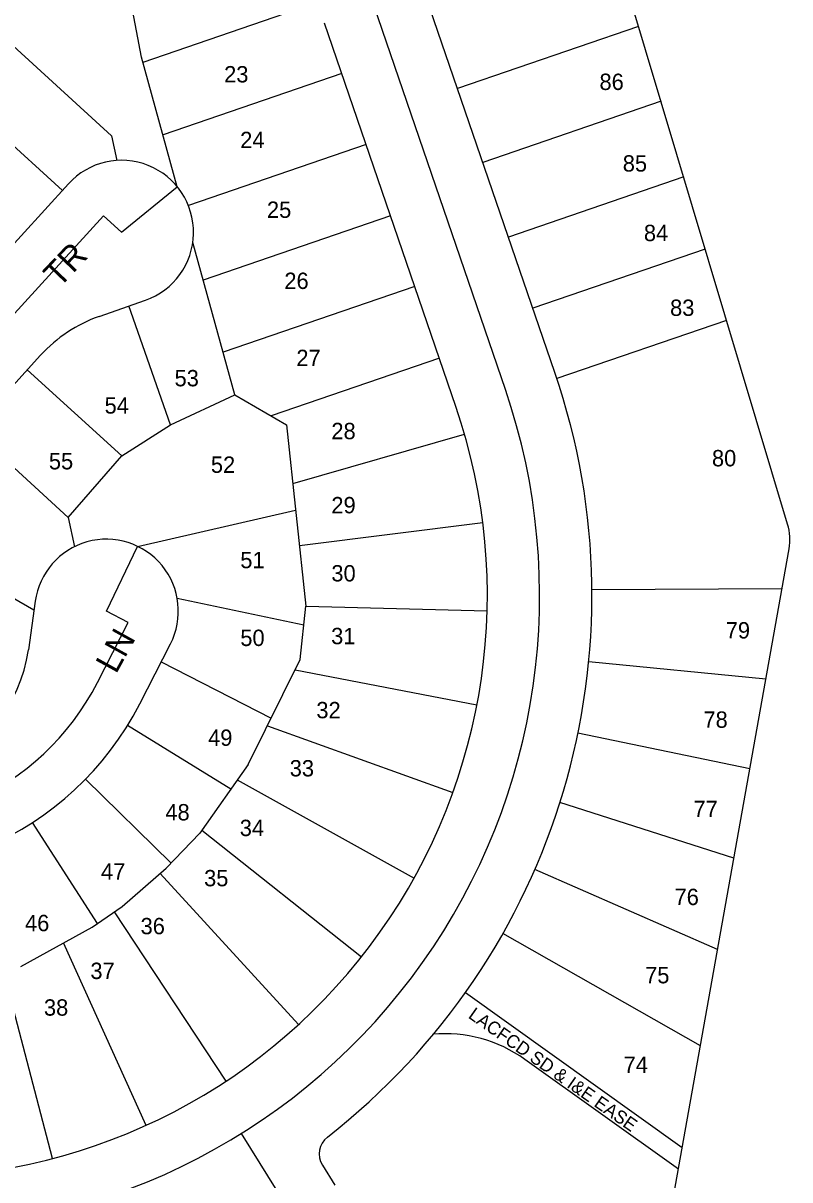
# Model space of a CAD drawing. Extents: x 6387474 to 6390971, y 1972046 to 1973920.
# Drawn here: x 6389408 to 6389877, y 1972544 to 1973251 of the extents above; entities that cross this region are included whole.
import ezdxf

# ---------------------------------------------------------------- set-up
doc = ezdxf.new("R2010")
doc.units = 0
for name, color, linetype in [('1', 7, 'Continuous'), ('2', 7, 'Continuous'), ('3', 7, 'Continuous'), ('4', 7, 'Continuous'), ('5', 7, 'Continuous'), ('7', 7, 'Continuous')]:
    doc.layers.add(name, color=color, linetype=linetype)

msp = doc.modelspace()

# ---------------------------------------------------------------- linework, layer by layer
at = {"layer": '1'}
for p, q in [((6389875.29, 1972944.72), (6389740.69, 1973394.07)), ((6389759.25, 1972274.95), (6389876.15, 1972929.69))]:
    msp.add_line(p, q, dxfattribs=at)
msp.add_arc((6389844.16, 1972935.4), 32.5, 349.87611, 16.67291, dxfattribs=at)
at = {"layer": '2'}
for p, q in [((6389702.59, 1973027.14), (6389622.23, 1973261.52)), ((6389467.81, 1973123.26), (6389501.88, 1973151.11)), ((6389350.37, 1973016.66), (6389456.72, 1973133.37)), ((6389456.72, 1973133.37), (6389467.81, 1973123.26)), ((6389458.5, 1972891.57), (6389477.61, 1972931.2)), ((6389471.85, 1972884.72), (6389458.5, 1972891.57)), ((6389453.05, 1972848.05), (6389471.85, 1972884.72)), ((6389540.91, 1972572.1), (6389571.1, 1972523.69))]:
    msp.add_line(p, q, dxfattribs=at)
for centre, radius, start, end in [((6389335.56, 1972901.3), 388, 270.34667, 18.92365), ((6389310.66, 1972921.02), 160, 255.09194, 332.86738)]:
    msp.add_arc(centre, radius, start, end, dxfattribs=at)
at = {"layer": '3'}
for p, q in [((6389461.63, 1973182.31), (6389072.67, 1973536.78)), ((6389431.59, 1973148.83), (6389073.04, 1973475.59)), ((6389479.97, 1973230.27), (6389463.19, 1973318.92)), ((6389587.7, 1973263.79), (6389480.83, 1973227.16)), ((6389784.1, 1973249.17), (6389673.32, 1973211.19)), ((6389501.88, 1973151.11), (6389479.97, 1973230.27)), ((6389602.55, 1973220.27), (6389493.12, 1973182.75)), ((6389797.82, 1973203.34), (6389688.82, 1973165.97)), ((6389461.63, 1973182.31), (6389464.96, 1973167.17)), ((6389617.39, 1973176.98), (6389508.63, 1973139.69)), ((6389811.68, 1973157.08), (6389704.47, 1973120.32)), ((6389632.39, 1973133.23), (6389517.73, 1973093.92)), ((6389537.14, 1973023.81), (6389511.36, 1973116.96)), ((6389824.9, 1973112.96), (6389719.4, 1973076.79)), ((6389647.18, 1973090.09), (6389529.92, 1973049.89)), ((6389497.8, 1973005.51), (6389472.27, 1973078.19)), ((6389837.95, 1973069.4), (6389734.12, 1973033.8)), ((6389662.21, 1973046.24), (6389559.25, 1973010.94)), ((6389467.88, 1972986.49), (6389410.1, 1973039.15)), ((6389497.8, 1973005.51), (6389537.14, 1973023.81)), ((6389537.14, 1973023.81), (6389568.62, 1973005.49)), ((6389435.19, 1972948.92), (6389376.6, 1973002.32)), ((6389467.88, 1972986.49), (6389497.8, 1973005.51)), ((6389568.62, 1973005.49), (6389580.57, 1972894.73)), ((6389572.49, 1972969.58), (6389677.64, 1972999.89)), ((6389435.19, 1972948.92), (6389467.88, 1972986.49)), ((6389477.61, 1972931.2), (6389574.24, 1972953.37)), ((6389435.19, 1972948.92), (6389438.99, 1972931.01)), ((6389576.59, 1972931.67), (6389688.77, 1972945.82)), ((6389327.99, 1972942.3), (6389414.18, 1972892.32)), ((6389871.79, 1972905.24), (6389755.55, 1972904.52)), ((6389579.32, 1972883.05), (6389501.8, 1972899.34)), ((6389577.07, 1972861.96), (6389580.57, 1972894.73)), ((6389580.57, 1972894.73), (6389691.43, 1972891.77)), ((6389492.05, 1972860.55), (6389559.27, 1972826.11)), ((6389545.23, 1972797.84), (6389577.07, 1972861.96)), ((6389861.92, 1972849.96), (6389753.59, 1972860.66)), ((6389573.94, 1972855.67), (6389685.21, 1972834.37)), ((6389534.62, 1972782.8), (6389471.49, 1972821.75)), ((6389556.99, 1972821.53), (6389670.49, 1972780.65)), ((6389852.15, 1972795.24), (6389747.01, 1972816.96)), ((6389545.23, 1972797.84), (6389515.64, 1972755.89)), ((6389498.05, 1972737.54), (6389445.71, 1972788.8)), ((6389538.59, 1972788.43), (6389646.71, 1972728.33)), ((6389842.4, 1972740.64), (6389735.97, 1972774.52)), ((6389453.11, 1972700.64), (6389413.27, 1972762.3)), ((6389495.15, 1972734.52), (6389515.69, 1972755.91)), ((6389516.83, 1972757.58), (6389614.55, 1972680.16)), ((6389468.1, 1972710.93), (6389495.15, 1972734.52)), ((6389576.07, 1972638.83), (6389491.35, 1972731.23)), ((6389832.42, 1972684.77), (6389720.64, 1972733.64)), ((6389449.77, 1972698.35), (6389468.1, 1972710.93)), ((6389531.81, 1972604.28), (6389463.42, 1972707.74)), ((6389406.07, 1972674.39), (6389449.77, 1972698.35)), ((6389482.78, 1972577.17), (6389432.14, 1972688.69)), ((6389821.9, 1972625.84), (6389701.09, 1972694.44)), ((6389425.58, 1972556.87), (6389395.79, 1972670.93)), ((6389810.75, 1972563.4), (6389678.1, 1972658.27))]:
    msp.add_line(p, q, dxfattribs=at)
at = {"layer": '4'}
for p, q in [((6389732.86, 1973037.51), (6389652.51, 1973271.9)), ((6389672.32, 1973016.76), (6389591.96, 1973251.15)), ((6389328.93, 1973036.19), (6389435.29, 1973152.9)), ((6389454.09, 1973071.8), (6389482.39, 1973081.75)), ((6389371.8, 1972997.13), (6389418.21, 1973048.05)), ((6389414.92, 1972897.62), (6389410.79, 1972867.91)), ((6389478.86, 1972834.82), (6389497.66, 1972871.5)), ((6389590.63, 1972552.84), (6389598.25, 1972540.63))]:
    msp.add_line(p, q, dxfattribs=at)
for centre, radius, start, end in [((6389467.81, 1973123.26), 44, 289.35556, 137.65176), ((6389483.25, 1972988.78), 88, 109.35274, 137.65556), ((6389335.56, 1972901.3), 420, 307.91924, 18.92365), ((6389335.56, 1972901.3), 356, 270.34667, 18.92365), ((6389458.5, 1972891.57), 44, 332.86889, 172.08892), ((6389323.62, 1972880.02), 88, 287.54705, 352.08944), ((6389310.66, 1972921.02), 189, 253.67626, 332.86738), ((6389601.66, 1972559.72), 13, 127.91924, 211.95472)]:
    msp.add_arc(centre, radius, start, end, dxfattribs=at)
at = {"layer": '5'}
msp.add_line((6389808.42, 1972550.32), (6389714.47, 1972617.51), dxfattribs=at)
msp.add_arc((6389665.6, 1972549.18), 84, 54.42917, 95.08871, dxfattribs=at)

# ---------------------------------------------------------------- texts
at = {"layer": '2'}
for s, rotation, p in [('TR', 46.4755, (6389429.58, 1973088.82)), ('LN', 61.11398, (6389464.37, 1972852.71))]:
    msp.add_text(s, height=15, rotation=rotation, dxfattribs=at).set_placement(p)
at = {"layer": '5'}
msp.add_text('LACFCD SD & I&E EASE', height=8, rotation=324.92558, dxfattribs=at).set_placement((6389679.36, 1972643.24))
at = {"layer": '7'}
for s, p in [('23', (6389530.51, 1973214.89)), ('86', (6389760.17, 1973210.26)), ('24', (6389540.34, 1973174.7)), ('85', (6389774.42, 1973160.37)), ('25', (6389556.72, 1973132.06)), ('84', (6389787.33, 1973117.86)), ('26', (6389567.37, 1973088.59)), ('83', (6389803.36, 1973072.12)), ('27', (6389574.71, 1973041.44)), ('53', (6389500.19, 1973029.06)), ('54', (6389457.38, 1973012.38)), ('28', (6389596.13, 1972996.73)), ('55', (6389423.29, 1972978.27)), ('52', (6389522.41, 1972976.16)), ('80', (6389828.99, 1972980.13)), ('29', (6389596.13, 1972951.4)), ('51', (6389540.42, 1972917.84)), ('30', (6389596.13, 1972909.75)), ('50', (6389540.42, 1972870.27)), ('31', (6389595.99, 1972871.37)), ('79', (6389837.41, 1972874.87)), ('32', (6389586.95, 1972826.08)), ('78', (6389823.77, 1972820.27)), ('49', (6389520.7, 1972809.22)), ('33', (6389570.65, 1972790.52)), ('48', (6389494.56, 1972763.62)), ('77', (6389817.66, 1972765.66)), ('34', (6389540.08, 1972754.05)), ('47', (6389455.18, 1972727.43)), ('35', (6389518.26, 1972723.34)), ('76', (6389806.09, 1972711.86)), ('46', (6389408.69, 1972695.87)), ('36', (6389479.4, 1972694.01)), ('37', (6389448.69, 1972666.65)), ('75', (6389788.09, 1972664.01)), ('38', (6389420.28, 1972644.23)), ('74', (6389774.96, 1972609.26))]:
    msp.add_text(s, height=10, dxfattribs=at).set_placement(p)

doc.saveas('drawing.dxf')
